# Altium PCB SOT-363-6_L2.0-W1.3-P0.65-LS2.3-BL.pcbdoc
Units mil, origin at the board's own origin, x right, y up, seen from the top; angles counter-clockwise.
Board outline 598.31 x 607.87 mil, 2 copper layers (Top Layer, Bottom Layer), stack 0 mil thick; 1 components, 0 nets, 6 pads, 0 vias.
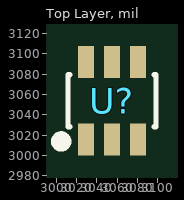
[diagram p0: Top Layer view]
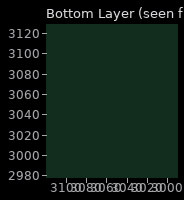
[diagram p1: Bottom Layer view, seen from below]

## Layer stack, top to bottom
Top Layer: signal copper (thickness not stored)
Bottom Layer: signal copper (thickness not stored)

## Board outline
3348.31,2750 2750,2750 2750,3357.87 3348.31,3357.87

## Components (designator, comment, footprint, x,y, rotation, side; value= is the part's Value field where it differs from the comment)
U? "" SOT-363-6_L2.0-W1.3-P0.65-LS2.3-BL 3055,3053.93 r0 top

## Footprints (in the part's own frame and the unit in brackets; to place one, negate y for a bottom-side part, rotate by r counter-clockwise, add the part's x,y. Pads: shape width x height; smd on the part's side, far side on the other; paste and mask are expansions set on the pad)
SOT-363-6_L2.0-W1.3-P0.65-LS2.3-BL [mm]
  rect 0.4x0.8 smd paste+0 mask+0.05: 1(-0.65,-0.97) 2(0,-0.97) 3(0.65,-0.97) 4(0.65,0.97) 5(0,0.97) 6(-0.65,0.97)
  silkscreen extent -1.4,-1.14 1.1,0.65

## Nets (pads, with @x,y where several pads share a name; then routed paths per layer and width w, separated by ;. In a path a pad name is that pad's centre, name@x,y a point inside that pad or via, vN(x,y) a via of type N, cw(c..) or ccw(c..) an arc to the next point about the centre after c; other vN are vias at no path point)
pads on no net: U?.1 U?.2 U?.3 U?.4 U?.5 U?.6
